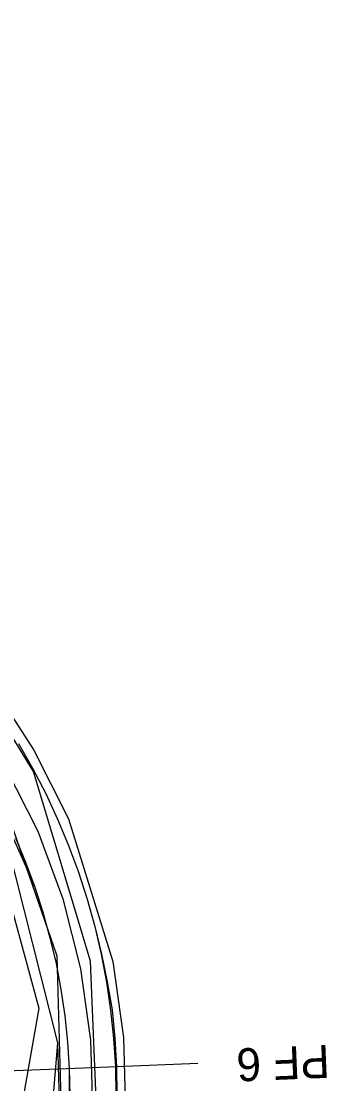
# Model space of a CAD drawing. Extents: x -555887 to -552101, y -1100251 to -1096546.
# Drawn here: x -553881.8 to -553858.7, y -1097525.5 to -1097444.9 of the extents above; entities that cross this region are included whole.
import ezdxf

# ---------------------------------------------------------------- set-up
doc = ezdxf.new("R2010")
doc.units = 0
for name, color, linetype in [('PARCELY_cesty', 7, 'Continuous'), ('PARCELY_VHO', 7, 'Continuous'), ('POLYGONY_SITUACE_PF', 7, 'Continuous'), ('POLYGONY_SITUACE_PF_POPISY', 7, 'Continuous'), ('POLYGONY_SITUACE_PO', 7, 'Continuous'), ('ZSST', 7, 'Continuous')]:
    doc.layers.add(name, color=color, linetype=linetype)

msp = doc.modelspace()

# ---------------------------------------------------------------- linework, layer by layer
at = {"layer": 'PARCELY_cesty'}
for points in [[(-554024.87, -1097326.1), (-554016.972, -1097335.203), (-554014.45, -1097338.793), (-554010.977, -1097346.054), (-554009.652, -1097347.922), (-554006.027, -1097351.272), (-553987.32, -1097361.268), (-553980.262, -1097366.544), (-553973.944, -1097372.641), (-553970.267, -1097377.21), (-553883.981, -1097495.416), (-553880.888, -1097500.181), (-553878.272, -1097505.378), (-553874.899, -1097516.211), (-553874.102, -1097521.974), (-553873.943, -1097527.652), (-553875.23, -1097592.292), (-553875.224, -1097601.67), (-553872.69, -1097624.12), (-553866.22, -1097627.85), (-553859.38, -1097625.46)], [(-554028.81, -1097333.03), (-554018.781, -1097341.326), (-554015.89, -1097351.24), (-554008.949, -1097355.38), (-553990.01, -1097365.499), (-553983.508, -1097370.361), (-553977.642, -1097376.021), (-553974.236, -1097380.253), (-553888.1, -1097498.254), (-553882.924, -1097507.258), (-553879.092, -1097522.388), (-553878.944, -1097527.655), (-553880.675, -1097592.231), (-553880.657, -1097599.68), (-553880.289, -1097607.162), (-553873.9, -1097664.18)]]:
    msp.add_lwpolyline(points, dxfattribs=at)
at = {"layer": 'PARCELY_VHO'}
msp.add_lwpolyline([(-554141.5, -1097107.04), (-554133.09, -1097133.96), (-554115.31, -1097177.28), (-554094.19, -1097204.11), (-554083.82, -1097222.99), (-554081.04, -1097249.03), (-554076.85, -1097264.17), (-554065.58, -1097288.03), (-554046.65, -1097316.45), (-554038.74, -1097323.54), (-554028.81, -1097333.03), (-554018.781, -1097341.326), (-554015.89, -1097351.24), (-554008.949, -1097355.38), (-553990.01, -1097365.499), (-553983.508, -1097370.361), (-553977.642, -1097376.021), (-553888.1, -1097498.254), (-553882.924, -1097507.258), (-553879.092, -1097522.388), (-553886.84, -1097615.05), (-553883.68, -1097641.57), (-553876.67, -1097669.5)], dxfattribs=at)
at = {"layer": 'POLYGONY_SITUACE_PF'}
for p, q in [((-553876.467, -1097524.272), (-553884.461, -1097524.599)), ((-553868.474, -1097523.945), (-553876.467, -1097524.272))]:
    msp.add_line(p, q, dxfattribs=at)
at = {"layer": 'POLYGONY_SITUACE_PO'}
for p, q in [((-553882.066, -1097499.671), (-553880.994, -1097501.542)), ((-553882.066, -1097499.671), (-553880.994, -1097501.542)), ((-553882.066, -1097499.671), (-553880.994, -1097501.542)), ((-553883.059, -1097501.427), (-553880.598, -1097506.318)), ((-553880.994, -1097501.542), (-553880, -1097503.456)), ((-553880.994, -1097501.542), (-553880, -1097503.456)), ((-553880.994, -1097501.542), (-553880, -1097503.456)), ((-553880, -1097503.456), (-553879.093, -1097505.411)), ((-553880, -1097503.456), (-553879.093, -1097505.411)), ((-553880, -1097503.456), (-553879.093, -1097505.411)), ((-553879.093, -1097505.411), (-553878.261, -1097507.4)), ((-553879.093, -1097505.411), (-553878.261, -1097507.4)), ((-553879.093, -1097505.411), (-553878.261, -1097507.4)), ((-553880.598, -1097506.318), (-553878.687, -1097511.449)), ((-553882.444, -1097506.891), (-553881.627, -1097508.722)), ((-553882.294, -1097506.825), (-553881.519, -1097508.68)), ((-553882.294, -1097506.825), (-553881.519, -1097508.68)), ((-553878.261, -1097507.4), (-553877.514, -1097509.423)), ((-553878.261, -1097507.4), (-553877.514, -1097509.423)), ((-553878.261, -1097507.4), (-553877.514, -1097509.423)), ((-553881.627, -1097508.722), (-553880.823, -1097510.565)), ((-553881.519, -1097508.68), (-553880.823, -1097510.565)), ((-553881.519, -1097508.68), (-553880.823, -1097510.565)), ((-553877.514, -1097509.423), (-553876.853, -1097511.474)), ((-553877.514, -1097509.423), (-553876.853, -1097511.474)), ((-553877.514, -1097509.423), (-553876.853, -1097511.474)), ((-553880.823, -1097510.565), (-553880.206, -1097512.478)), ((-553880.823, -1097510.565), (-553880.206, -1097512.478)), ((-553880.823, -1097510.565), (-553880.823, -1097510.565)), ((-553880.823, -1097510.565), (-553880.206, -1097512.478)), ((-553878.687, -1097511.449), (-553877.347, -1097516.758)), ((-553876.853, -1097511.474), (-553876.28, -1097513.553)), ((-553876.853, -1097511.474), (-553876.28, -1097513.553)), ((-553876.853, -1097511.474), (-553876.28, -1097513.553)), ((-553880.206, -1097512.478), (-553879.672, -1097514.416)), ((-553880.206, -1097512.478), (-553879.672, -1097514.416)), ((-553880.206, -1097512.478), (-553879.672, -1097514.416)), ((-553876.28, -1097513.553), (-553876.28, -1097513.553)), ((-553876.28, -1097513.553), (-553875.757, -1097515.646)), ((-553876.28, -1097513.553), (-553875.788, -1097515.652)), ((-553876.28, -1097513.553), (-553875.788, -1097515.652)), ((-553879.672, -1097514.416), (-553879.213, -1097516.373)), ((-553879.672, -1097514.416), (-553879.213, -1097516.373)), ((-553879.672, -1097514.416), (-553879.213, -1097516.373)), ((-553875.788, -1097515.652), (-553875.386, -1097517.77)), ((-553875.788, -1097515.652), (-553875.386, -1097517.77)), ((-553875.757, -1097515.646), (-553875.332, -1097517.761)), ((-553879.213, -1097516.373), (-553878.838, -1097518.348)), ((-553879.213, -1097516.373), (-553878.838, -1097518.348)), ((-553879.213, -1097516.373), (-553878.838, -1097518.348)), ((-553877.347, -1097516.758), (-553876.597, -1097522.181)), ((-553875.386, -1097517.77), (-553875.073, -1097519.904)), ((-553875.386, -1097517.77), (-553875.073, -1097519.904)), ((-553875.332, -1097517.761), (-553874.967, -1097519.89)), ((-553878.838, -1097518.348), (-553878.546, -1097520.337)), ((-553878.838, -1097518.348), (-553878.546, -1097520.337)), ((-553878.838, -1097518.348), (-553878.546, -1097520.337)), ((-553875.073, -1097519.904), (-553874.849, -1097522.048)), ((-553875.073, -1097519.904), (-553874.849, -1097522.048)), ((-553874.967, -1097519.89), (-553874.746, -1097522.039)), ((-553878.546, -1097520.337), (-553878.337, -1097522.337)), ((-553878.546, -1097520.337), (-553878.337, -1097522.337)), ((-553878.546, -1097520.337), (-553878.337, -1097522.337)), ((-553878.337, -1097522.337), (-553878.216, -1097524.343)), ((-553878.337, -1097522.337), (-553878.216, -1097524.343)), ((-553878.337, -1097522.337), (-553878.337, -1097522.337)), ((-553878.337, -1097522.337), (-553878.216, -1097524.343)), ((-553876.597, -1097522.181), (-553876.443, -1097527.654)), ((-553874.849, -1097522.048), (-553874.719, -1097524.2)), ((-553874.849, -1097522.048), (-553874.719, -1097524.2)), ((-553874.746, -1097522.039), (-553874.642, -1097524.197)), ((-553874.719, -1097524.2), (-553874.677, -1097526.356)), ((-553874.719, -1097524.2), (-553874.677, -1097526.356)), ((-553874.642, -1097524.197), (-553874.593, -1097526.356)), ((-553878.215, -1097524.37), (-553878.219, -1097526.353)), ((-553878.216, -1097524.343), (-553878.177, -1097526.353)), ((-553878.216, -1097524.343), (-553878.177, -1097526.353)), ((-553878.216, -1097524.343), (-553878.215, -1097524.37))]:
    msp.add_line(p, q, dxfattribs=at)
at = {"layer": 'ZSST'}
for points in [[(-553869.95, -1097682.22), (-553871.05, -1097647.6), (-553870.2, -1097626.99), (-553876.84, -1097598.04), (-553877.64, -1097579), (-553875.72, -1097537.7), (-553876.59, -1097516.18), (-553880.93, -1097501.8), (-553888.19, -1097489.91), (-553910.46, -1097459.06), (-553932.29, -1097430.48), (-553957.48, -1097396.42), (-553968.04, -1097383.84), (-553976.57, -1097371.28), (-553984.26, -1097363.91), (-554005.86, -1097353.41), (-554012.69, -1097347.14), (-554017.87, -1097337.24)], [(-554020.91, -1097340.19), (-554015.31, -1097348.85), (-554006.92, -1097355.66), (-553985.92, -1097365.87), (-553978.11, -1097373.02), (-553970.29, -1097385.01), (-553959.09, -1097398.12), (-553934.58, -1097431.99), (-553912.45, -1097460.83), (-553890.61, -1097491.11), (-553883.62, -1097502.9), (-553879.16, -1097515.79), (-553878.55, -1097537.65), (-553880.23, -1097578.32), (-553879.49, -1097598.53), (-553872.4, -1097626.72), (-553873.46, -1097647.68), (-553872.28, -1097682.24)], [(-553899.81, -1097482.01), (-553884.98, -1097503.36), (-553880.51, -1097519.75), (-553882.93, -1097533.43), (-553886.31, -1097546.7), (-553888.25, -1097579.38), (-553889.22, -1097595.62), (-553890, -1097613.32), (-553886.41, -1097640.12), (-553879.65, -1097659.4)]]:
    msp.add_lwpolyline(points, dxfattribs=at)

# ---------------------------------------------------------------- texts
at = {"layer": 'POLYGONY_SITUACE_PF_POPISY'}
msp.add_text('PF 6', height=2.5, rotation=182.34162, dxfattribs=at).set_placement((-553858.523, -1097522.537))

doc.saveas('drawing.dxf')
